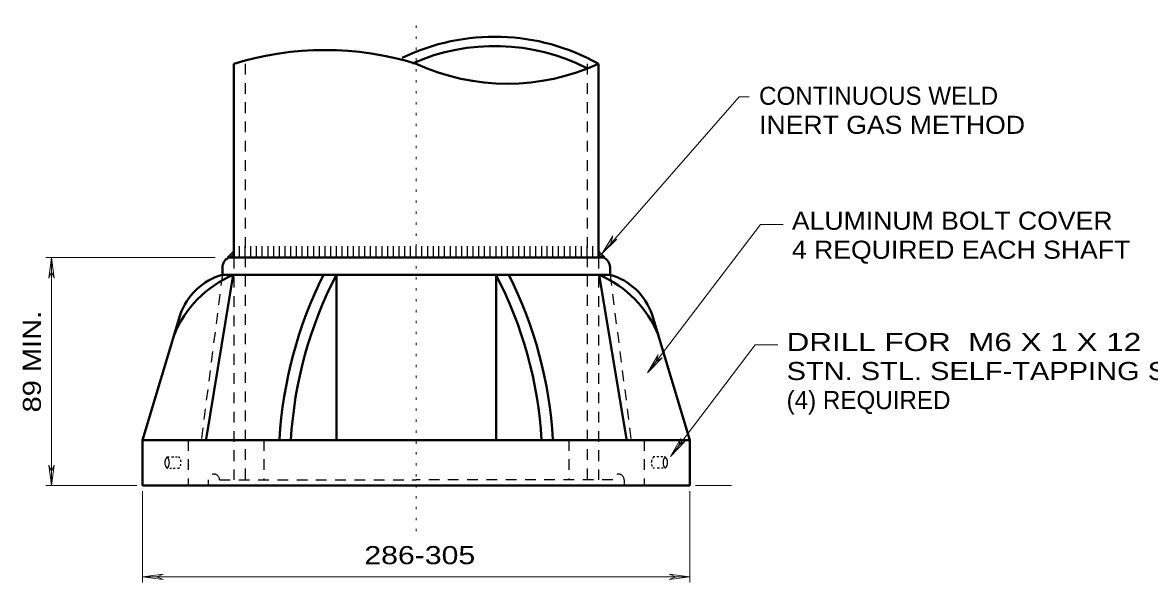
# Model space of a CAD drawing. Extents: x 312583 to 312854, y 144419 to 144597.
# Drawn here: x 312675.75 to 312723.12, y 144468.05 to 144491.58 of the extents above; entities that cross this region are included whole.
import ezdxf

# ---------------------------------------------------------------- set-up
doc = ezdxf.new("R2010")
doc.units = 0
doc.header["$LTSCALE"] = 0.3
doc.linetypes.add('DOTTED', pattern=[1.5, 0.3, -1.2])
doc.linetypes.add('SHORT_DASHED', pattern=[2.7, 1.5, -1.2])
doc.layers.add('1', color=7, linetype='Continuous', lineweight=35)
doc.layers.add('2', color=7, linetype='Continuous', lineweight=13)

msp = doc.modelspace()

# ---------------------------------------------------------------- linework, layer by layer
at = {"layer": '1', "lineweight": 40}
for p, q in [((312684.6288, 144489.8523), (312684.6288, 144481.7026)), ((312699.9621, 144489.8523), (312699.9621, 144481.7026)), ((312684.4141, 144481.7026), (312692.2955, 144481.7026)), ((312700.1845, 144481.7026), (312692.2955, 144481.7026)), ((312684.1535, 144481.3116), (312684.1535, 144480.982)), ((312700.4451, 144481.3116), (312700.4451, 144480.982)), ((312684.5981, 144480.9743), (312683.4635, 144474.0743)), ((312684.1535, 144480.982), (312692.2955, 144480.982)), ((312688.9451, 144480.982), (312688.9451, 144474.036)), ((312700.4451, 144480.982), (312692.2955, 144480.982)), ((312695.6535, 144480.982), (312695.6535, 144474.036)), ((312699.9928, 144480.9743), (312701.1351, 144474.0743)), ((312682.3748, 144479.2953), (312680.7955, 144474.036)), ((312702.2161, 144479.2953), (312703.7955, 144474.036)), ((312680.7955, 144474.036), (312680.7955, 144472.1193)), ((312680.7955, 144474.036), (312692.2955, 144474.036)), ((312703.7955, 144474.036), (312692.2955, 144474.036)), ((312703.7955, 144474.036), (312703.7955, 144472.1193)), ((312680.7955, 144472.1193), (312692.2955, 144472.1193)), ((312703.7955, 144472.1193), (312692.2955, 144472.1193))]:
    msp.add_line(p, q, dxfattribs=at)
at = {"layer": '1', "linetype": 'SHORT_DASHED', "lineweight": 25}
for p, q in [((312685.1118, 144489.8523), (312685.1118, 144472.357)), ((312699.4868, 144489.8523), (312699.4868, 144472.357)), ((312684.6288, 144481.7026), (312684.6288, 144472.357)), ((312699.9621, 144481.7026), (312699.9621, 144472.357)), ((312684.1458, 144480.9743), (312683.2641, 144474.0743)), ((312700.4451, 144480.9743), (312701.3268, 144474.0743)), ((312682.7121, 144474.036), (312682.7121, 144472.0886)), ((312685.8861, 144474.036), (312685.8861, 144472.3646)), ((312698.7048, 144474.036), (312698.7048, 144472.3646)), ((312701.8788, 144474.036), (312701.8788, 144472.0886)), ((312681.8228, 144473.323), (312681.9071, 144473.323)), ((312682.1831, 144473.323), (312682.2521, 144473.323)), ((312682.2981, 144473.323), (312682.3135, 144473.323)), ((312702.3311, 144473.323), (312702.2775, 144473.323)), ((312702.4998, 144473.323), (312702.4078, 144473.323)), ((312702.6608, 144473.323), (312702.5765, 144473.323)), ((312702.7681, 144473.323), (312702.7298, 144473.323)), ((312681.8228, 144472.8476), (312681.8611, 144472.8476)), ((312681.9378, 144472.8476), (312682.0145, 144472.8476)), ((312682.0835, 144472.8476), (312682.0911, 144472.8476)), ((312682.0911, 144472.8476), (312682.1601, 144472.8476)), ((312682.2598, 144472.8476), (312682.3135, 144472.8476)), ((312702.3158, 144472.8476), (312702.2775, 144472.8476)), ((312702.4998, 144472.8476), (312702.4231, 144472.8476)), ((312702.5228, 144472.8476), (312702.4998, 144472.8476)), ((312702.6838, 144472.8476), (312702.6071, 144472.8476)), ((312702.7681, 144472.8476), (312702.7528, 144472.8476)), ((312683.5555, 144472.357), (312683.5555, 144472.1193)), ((312684.0308, 144472.357), (312692.2955, 144472.357)), ((312700.5601, 144472.357), (312692.2955, 144472.357)), ((312701.0431, 144472.357), (312701.0431, 144472.1193))]:
    msp.add_line(p, q, dxfattribs=at)
at = {"layer": '1', "lineweight": 25}
for p, q in [((312684.8665, 144481.7026), (312684.8665, 144482.1856)), ((312685.1118, 144481.7026), (312685.1118, 144482.1856)), ((312685.3495, 144481.7026), (312685.3495, 144482.1856)), ((312685.5871, 144481.7026), (312685.5871, 144482.1856)), ((312685.8248, 144481.7026), (312685.8248, 144482.1856)), ((312686.0701, 144481.7026), (312686.0701, 144482.1856)), ((312686.3078, 144481.7026), (312686.3078, 144482.1856)), ((312686.5455, 144481.7026), (312686.5455, 144482.1856)), ((312686.7831, 144481.7026), (312686.7831, 144482.1856)), ((312687.0285, 144481.7026), (312687.0285, 144482.1856)), ((312687.2661, 144481.7026), (312687.2661, 144482.1856)), ((312687.5038, 144481.7026), (312687.5038, 144482.1856)), ((312687.7415, 144481.7026), (312687.7415, 144482.1856)), ((312687.9868, 144481.7026), (312687.9868, 144482.1856)), ((312688.2245, 144481.7026), (312688.2245, 144482.1856)), ((312688.4621, 144481.7026), (312688.4621, 144482.1856)), ((312688.6998, 144481.7026), (312688.6998, 144482.1856)), ((312688.9451, 144481.7026), (312688.9451, 144482.1856)), ((312689.1828, 144481.7026), (312689.1828, 144482.1856)), ((312689.4205, 144481.7026), (312689.4205, 144482.1856)), ((312689.6581, 144481.7026), (312689.6581, 144482.1856)), ((312689.9035, 144481.7026), (312689.9035, 144482.1856)), ((312690.1411, 144481.7026), (312690.1411, 144482.1856)), ((312690.3788, 144481.7026), (312690.3788, 144482.1856)), ((312690.6165, 144481.7026), (312690.6165, 144482.1856)), ((312690.8618, 144481.7026), (312690.8618, 144482.1856)), ((312691.0995, 144481.7026), (312691.0995, 144482.1856)), ((312691.3371, 144481.7026), (312691.3371, 144482.1856)), ((312691.5748, 144481.7026), (312691.5748, 144482.1856)), ((312691.8201, 144481.7026), (312691.8201, 144482.1856)), ((312692.0578, 144481.7026), (312692.0578, 144482.1856)), ((312692.2955, 144481.7026), (312692.2955, 144482.1856)), ((312692.2955, 144481.7026), (312692.2955, 144482.1856)), ((312692.5331, 144481.7026), (312692.5331, 144482.1856)), ((312692.7785, 144481.7026), (312692.7785, 144482.1856)), ((312693.0161, 144481.7026), (312693.0161, 144482.1856)), ((312693.2538, 144481.7026), (312693.2538, 144482.1856)), ((312693.4915, 144481.7026), (312693.4915, 144482.1856)), ((312693.7368, 144481.7026), (312693.7368, 144482.1856)), ((312693.9745, 144481.7026), (312693.9745, 144482.1856)), ((312694.2121, 144481.7026), (312694.2121, 144482.1856)), ((312694.4498, 144481.7026), (312694.4498, 144482.1856)), ((312694.6951, 144481.7026), (312694.6951, 144482.1856)), ((312694.9328, 144481.7026), (312694.9328, 144482.1856)), ((312695.1705, 144481.7026), (312695.1705, 144482.1856)), ((312695.4081, 144481.7026), (312695.4081, 144482.1856)), ((312695.6535, 144481.7026), (312695.6535, 144482.1856)), ((312695.8911, 144481.7026), (312695.8911, 144482.1856)), ((312696.1288, 144481.7026), (312696.1288, 144482.1856)), ((312696.3665, 144481.7026), (312696.3665, 144482.1856)), ((312696.6118, 144481.7026), (312696.6118, 144482.1856)), ((312696.8495, 144481.7026), (312696.8495, 144482.1856)), ((312697.0871, 144481.7026), (312697.0871, 144482.1856)), ((312697.3248, 144481.7026), (312697.3248, 144482.1856)), ((312697.5701, 144481.7026), (312697.5701, 144482.1856)), ((312697.8078, 144481.7026), (312697.8078, 144482.1856)), ((312698.0455, 144481.7026), (312698.0455, 144482.1856)), ((312698.2831, 144481.7026), (312698.2831, 144482.1856)), ((312698.5285, 144481.7026), (312698.5285, 144482.1856)), ((312698.7661, 144481.7026), (312698.7661, 144482.1856)), ((312699.0038, 144481.7026), (312699.0038, 144482.1856)), ((312699.2415, 144481.7026), (312699.2415, 144482.1856)), ((312699.4868, 144481.7026), (312699.4868, 144482.1856)), ((312699.7245, 144481.7026), (312699.7245, 144482.1856)), ((312684.3681, 144481.718), (312684.6211, 144481.971)), ((312700.2228, 144481.718), (312699.9698, 144481.971))]:
    msp.add_line(p, q, dxfattribs=at)
at = {"layer": '1', "linetype": 'SHORT_DASHED', "lineweight": 25}
msp.add_lwpolyline([(312682.0145, 144473.323), (312682.0911, 144473.323), (312682.1065, 144473.323)], dxfattribs=at)
at = {"layer": '1', "lineweight": 40}
for centre, radius, start, end in [((312695.5931, 144482.0648), 8.926, 60.69422, 115.82229), ((312695.5931, 144482.0648), 8.5322, 62.9999, 113.82364), ((312688.4621, 144477.4993), 12.9304, 72.75496, 107.24505), ((312696.1288, 144498.2127), 9.2008, 245.37787, 294.62213), ((312684.6224, 144481.2787), 0.4741, 116.58003, 175.77969), ((312699.9685, 144481.2787), 0.4741, 4.22031, 63.41997), ((312686.4355, 144476.6938), 4.6607, 113.24341, 157.93971), ((312684.8664, 144478.4525), 2.6309, 105.80989, 161.27202), ((312704.296, 144473.0098), 17.781, 153.35491, 176.59885), ((312704.296, 144473.0098), 17.3018, 152.55593, 176.59975), ((312680.295, 144473.0098), 17.3018, 3.40025, 27.44407), ((312680.295, 144473.0098), 17.781, 3.40115, 26.64509), ((312698.1554, 144476.6938), 4.6607, 22.06029, 66.75659), ((312699.7245, 144478.4525), 2.6309, 18.72798, 74.19011)]:
    msp.add_arc(centre, radius, start, end, dxfattribs=at)
at = {"layer": '1', "lineweight": 25}
for centre, start, end in [((312682.0731, 144473.0853), 136.2573, 223.7427), ((312681.5725, 144473.0853), 316.2573, 43.7427), ((312703.0185, 144473.0853), 136.2573, 223.7427), ((312702.5178, 144473.0853), 316.2573, 43.7427)]:
    msp.add_arc(centre, 0.3465, start, end, dxfattribs=at)
at = {"layer": '1', "linetype": 'SHORT_DASHED', "lineweight": 25}
for centre, radius, start, end in [((312682.065, 144473.0853), 0.3465, 32.44033, 43.7427), ((312682.065, 144473.0853), 0.3465, 4.74763, 20.67331), ((312702.5259, 144473.0853), 0.3465, 159.73267, 178.10776), ((312702.5259, 144473.0853), 0.3465, 136.2573, 147.12156), ((312682.065, 144473.0853), 0.3465, 316.2573, 323.4354), ((312682.065, 144473.0853), 0.3465, 336.21237, 349.53207), ((312683.7912, 144472.3589), 0.2396, 0, 180), ((312700.7997, 144472.3589), 0.2396, 0, 180), ((312702.5259, 144473.0853), 0.3465, 194.06618, 205.77383), ((312702.5259, 144473.0853), 0.3465, 217.39149, 223.7427)]:
    msp.add_arc(centre, radius, start, end, dxfattribs=at)
at = {"layer": '2', "linetype": 'DOTTED'}
msp.add_line((312692.2955, 144470.2026), (312692.2955, 144491.585), dxfattribs=at)
at = {"layer": '2'}
for p, q in [((312705.8731, 144488.457), (312700.1078, 144481.8713)), ((312705.8731, 144488.457), (312706.2948, 144488.457)), ((312702.0245, 144476.8573), (312706.7625, 144483.0903)), ((312706.7625, 144483.0903), (312707.7208, 144483.0903)), ((312700.1078, 144481.8713), (312700.5678, 144482.615)), ((312700.5678, 144482.615), (312700.4758, 144482.3313)), ((312700.1078, 144481.8713), (312700.7288, 144482.4846)), ((312700.7288, 144482.4846), (312700.4758, 144482.3313)), ((312683.8468, 144481.7026), (312676.7245, 144481.7026)), ((312676.9621, 144481.7026), (312676.8548, 144480.8363)), ((312676.9621, 144472.1193), (312676.9621, 144481.7026)), ((312676.9621, 144481.7026), (312677.0695, 144480.8363)), ((312676.8548, 144480.8363), (312676.9621, 144481.1123)), ((312677.0695, 144480.8363), (312676.9621, 144481.1123)), ((312702.9828, 144473.346), (312706.5401, 144478.0303)), ((312706.5401, 144478.0303), (312707.4985, 144478.0303)), ((312702.0245, 144476.8573), (312702.4615, 144477.6163)), ((312702.0245, 144476.8573), (312702.6378, 144477.486)), ((312702.4615, 144477.6163), (312702.3848, 144477.3326)), ((312702.6378, 144477.486), (312702.3848, 144477.3326)), ((312702.9828, 144473.346), (312703.4198, 144474.105)), ((312702.9828, 144473.346), (312703.4198, 144474.105)), ((312703.4198, 144474.105), (312703.3355, 144473.8213)), ((312703.4198, 144474.105), (312703.3355, 144473.8213)), ((312702.9828, 144473.346), (312703.5885, 144473.9746)), ((312702.9828, 144473.346), (312703.5885, 144473.9746)), ((312703.5885, 144473.9746), (312703.3355, 144473.8213)), ((312703.5885, 144473.9746), (312703.3355, 144473.8213)), ((312676.8548, 144472.9856), (312676.9621, 144472.7096)), ((312676.9621, 144472.1193), (312676.8548, 144472.9856)), ((312677.0695, 144472.9856), (312676.9621, 144472.7096)), ((312676.9621, 144472.1193), (312677.0695, 144472.9856)), ((312680.5578, 144472.1193), (312676.7245, 144472.1193)), ((312704.0331, 144472.1193), (312705.5511, 144472.1193)), ((312680.7955, 144471.8816), (312680.7955, 144468.0483)), ((312703.7955, 144471.8816), (312703.7955, 144468.0483)), ((312680.7955, 144468.286), (312681.6618, 144468.3933)), ((312681.6618, 144468.3933), (312681.3858, 144468.286)), ((312702.9291, 144468.3933), (312703.2051, 144468.286)), ((312703.7955, 144468.286), (312702.9291, 144468.3933)), ((312680.7955, 144468.286), (312681.6618, 144468.1786)), ((312680.7955, 144468.286), (312692.2955, 144468.286)), ((312681.6618, 144468.1786), (312681.3858, 144468.286)), ((312703.7955, 144468.286), (312692.2955, 144468.286)), ((312702.9291, 144468.1786), (312703.2051, 144468.286)), ((312703.7955, 144468.286), (312702.9291, 144468.1786))]:
    msp.add_line(p, q, dxfattribs=at)
at = {"layer": '2', "lineweight": 25}
for p, q in [((312684.4295, 144481.7103), (312684.6135, 144481.8943)), ((312684.5215, 144481.7026), (312684.6058, 144481.787)), ((312699.9698, 144481.9556), (312699.9775, 144481.9633)), ((312699.9698, 144481.856), (312700.0311, 144481.9173)), ((312699.9698, 144481.764), (312700.0771, 144481.8636)), ((312700.0311, 144481.7333), (312700.1231, 144481.8176)), ((312700.1231, 144481.7256), (312700.1691, 144481.7716)), ((312700.2151, 144481.718), (312700.2151, 144481.7256))]:
    msp.add_line(p, q, dxfattribs=at)
at = {"layer": '2'}
for points in [[(312684.5981, 144481.695), (312684.3681, 144481.718), (312684.6211, 144481.971)], [(312699.9698, 144481.971), (312700.2228, 144481.718), (312699.9698, 144481.7333)]]:
    msp.add_lwpolyline(points, close=True, dxfattribs=at)

# ---------------------------------------------------------------- texts
for s, p in [('CONTINUOUS WELD', (312706.7088, 144488.1263)), ('(4) REQUIRED', (312707.8665, 144475.3363))]:
    msp.add_text(s, height=0.76, dxfattribs=at).set_placement(p)
for s, width, p in [('INERT GAS METHOD', 1.1, (312706.7088, 144486.9063)), ('ALUMINUM BOLT COVER', 1.1, (312708.0888, 144482.8746)), ('4 REQUIRED EACH SHAFT', 1.1, (312708.0888, 144481.6546)), ('DRILL FOR  M6 X 1 X 12', 1.3, (312707.8665, 144477.7763)), ('STN. STL. SELF-TAPPING SCR.', 1.2, (312707.8665, 144476.5563)), ('286-305 ', 1.25, (312690.1146, 144468.817))]:
    msp.add_text(s, height=0.76, dxfattribs=dict(at, width=width)).set_placement(p)
at = {"layer": '2', "width": 1.2}
msp.add_text('89 MIN.', height=0.76, rotation=90, dxfattribs=at).set_placement((312676.518, 144475.1964))

doc.saveas('drawing.dxf')
